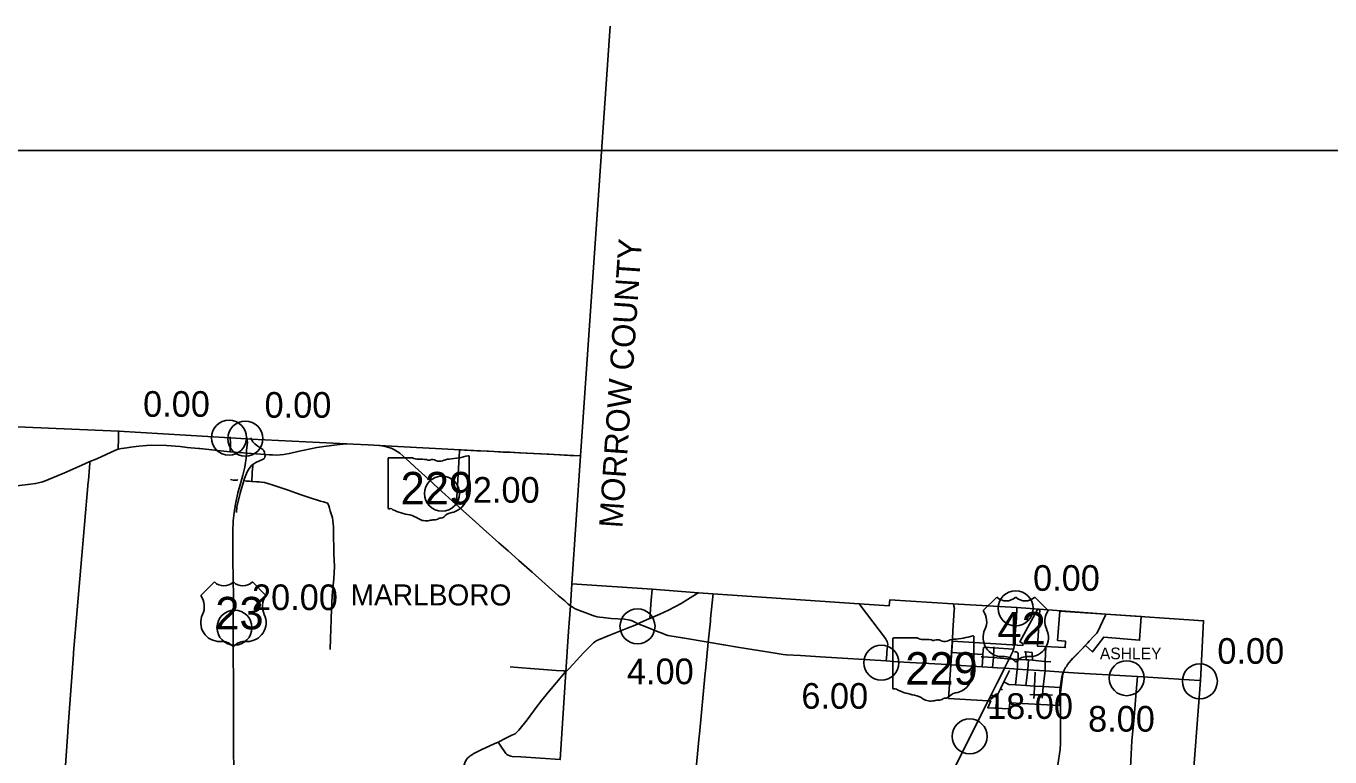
# Model space of a CAD drawing. Extents: x 1597222 to 1925846, y 496284 to 911751.
# Drawn here: x 1799698 to 1855559, y 874016 to 905333 of the extents above; entities that cross this region are included whole.
import ezdxf

# ---------------------------------------------------------------- set-up
doc = ezdxf.new("R2010")
doc.units = 0
for name, color, linetype in [('Default', 7, 'Continuous'), ('GM_X_Adjacent_County', 7, 'Continuous'), ('GM_X_Adjacent_County_Text', 7, 'Continuous'), ('GM_X_City_Street', 7, 'Continuous'), ('GM_X_Corporation', 7, 'Continuous'), ('GM_X_Corporation_Text', 7, 'Continuous'), ('GM_X_County', 7, 'Continuous'), ('GM_X_County_Road', 7, 'Continuous'), ('GM_X_State_Route', 7, 'Continuous'), ('GM_X_State_Shield', 7, 'Continuous'), ('GM_X_Township', 7, 'Continuous'), ('GM_X_Township_Road', 7, 'Continuous'), ('GM_X_Township_Text', 7, 'Continuous'), ('GM_X_US_Route', 7, 'Continuous'), ('GM_X_US_Shield', 7, 'Continuous'), ('SC_Scratch1', 7, 'Continuous')]:
    doc.layers.add(name, color=color, linetype=linetype)

msp = doc.modelspace()

# ---------------------------------------------------------------- linework, layer by layer
at = {"layer": 'Default'}
for centre in [(1808393, 887694), (1808393, 887694), (1809093, 887655), (1809093, 887655), (1817518, 885300), (1842090, 880384), (1842090, 880384), (1808627, 879557), (1825893, 879614), (1836343, 878055), (1846854, 877391), (1849986, 877257), (1849986, 877257), (1840121, 874896)]:
    msp.add_circle(centre, 750, dxfattribs=at)
at = {"layer": 'GM_X_Adjacent_County'}
msp.add_line((1823458, 886911), (1824723, 905333), dxfattribs=at)
at = {"layer": 'GM_X_City_Street'}
for points in [[(1845108, 878825), (1845186, 878908), (1845242, 878975), (1845432, 879171), (1845571, 879323), (1845601, 879368), (1845923, 880061), (1845958, 880137)], [(1840655, 877877), (1840684, 878302), (1840692, 878411), (1840712, 878711)], [(1840712, 878711), (1840771, 878720), (1841162, 878693), (1842005, 878635)], [(1841096, 877846), (1841141, 878272), (1841162, 878693), (1841165, 878729)], [(1843359, 877702), (1843365, 878107), (1843394, 878741)], [(1839341, 878485), (1840692, 878411)], [(1840624, 878310), (1840684, 878302), (1841141, 878272), (1841739, 878225)], [(1841739, 878225), (1841815, 878219), (1842196, 878198), (1842538, 878180), (1842649, 878172), (1842823, 878163), (1843332, 878109)], [(1842195, 878194), (1842196, 878198), (1842207, 878423), (1842204, 878453), (1842189, 878476), (1842156, 878505), (1842118, 878523), (1842051, 878515)], [(1842164, 877756), (1842167, 877780), (1842180, 877986), (1842195, 878194)], [(1842480, 878523), (1842536, 878518), (1842809, 878492)], [(1842531, 877075), (1842621, 877751), (1842649, 878172)], [(1842538, 878180), (1842536, 878518)], [(1842823, 878163), (1842809, 878492)], [(1841290, 876572), (1841275, 876591), (1841439, 876928), (1841591, 877241), (1841826, 877723)], [(1842082, 877102), (1842164, 877756)], [(1842882, 876677), (1842882, 876677), (1842882, 876684), (1842900, 877054), (1842928, 877653)], [(1843238, 876648), (1843241, 876673), (1843277, 877031), (1843359, 877702)], [(1843332, 878109), (1843335, 878108), (1843365, 878107), (1843598, 878093)], [(1841591, 877241), (1841805, 877127), (1842082, 877102), (1842094, 877101), (1842531, 877075), (1842900, 877054), (1843277, 877031), (1843995, 876989)], [(1841039, 876677), (1841303, 876558)], [(1841244, 876119), (1841303, 876558), (1841290, 876572)], [(1841439, 876928), (1841534, 876885)], [(1842709, 876689), (1842882, 876684), (1843220, 876674), (1843220, 876674)], [(1842875, 876522), (1842882, 876677)], [(1843220, 876674), (1843241, 876673), (1843680, 876660)], [(1843230, 876537), (1843238, 876642), (1843238, 876648)]]:
    msp.add_lwpolyline(points, dxfattribs=at)
at = {"layer": 'GM_X_Corporation'}
msp.add_lwpolyline([(1839212, 876522), (1839395, 878979), (1842403, 878797), (1842406, 878874), (1842276, 878944), (1843026, 880333), (1843137, 880326), (1843037, 878758), (1844222, 878701), (1844237, 878976), (1843894, 879006), (1843983, 880269), (1847478, 880034), (1847407, 879013), (1845866, 879149), (1845394, 878513), (1845080, 878796), (1844533, 878238), (1844393, 878064), (1844314, 877970), (1844271, 877898), (1844236, 877846), (1844178, 877730), (1844140, 877653), (1844101, 877578), (1844075, 877468), (1843989, 876865), (1843985, 876781), (1843972, 876227), (1841843, 876336), (1841816, 876073), (1840902, 876121), (1841027, 876414), (1840914, 876421)], close=True, dxfattribs=at)
at = {"layer": 'GM_X_County'}
msp.add_lwpolyline([(1797651, 888237), (1803655, 887971), (1808445, 887685), (1809126, 887642), (1809339, 887629), (1813443, 887429), (1813717, 887422), (1814360, 887388), (1814847, 887358), (1815353, 887328), (1818316, 887169), (1823458, 886911), (1823082, 881429), (1826517, 881205), (1828513, 881052), (1829123, 881005), (1835395, 880574), (1836682, 880495), (1836708, 880754), (1839410, 880574), (1842150, 880416), (1845959, 880135), (1850147, 879854), (1850017, 877290), (1849634, 872258)], dxfattribs=at)
at = {"layer": 'GM_X_County_Road'}
for points in [[(1802428, 886671), (1802725, 886790), (1803530, 887161), (1803639, 887203), (1803789, 887229), (1804010, 887263), (1804184, 887296), (1804528, 887326), (1804861, 887359), (1805077, 887369), (1805715, 887362), (1806296, 887312), (1806604, 887281), (1807079, 887231), (1807143, 887228), (1808298, 887102), (1808443, 887089)], [(1797502, 885545), (1798225, 885516), (1798393, 885518), (1798918, 885581), (1799416, 885645), (1799891, 885700), (1800108, 885729), (1800227, 885756), (1800345, 885789), (1800404, 885808), (1800482, 885836), (1801245, 886152), (1801314, 886180), (1802090, 886513), (1802428, 886671)], [(1801484, 875131), (1801730, 878401), (1801736, 878492), (1802364, 885806), (1802368, 885867), (1802423, 886605), (1802428, 886671)], [(1826404, 879946), (1826423, 879954), (1826844, 880138), (1827215, 880304), (1827767, 880596), (1828264, 880901), (1828526, 881056)], [(1826423, 879954), (1826479, 880739), (1826518, 881195)], [(1825923, 879717), (1825991, 879759), (1826404, 879946)], [(1822822, 877662), (1822979, 877822), (1823573, 878476), (1824013, 878909), (1824059, 878945), (1824151, 879002), (1824217, 879033), (1824631, 879211), (1825422, 879515), (1825871, 879688), (1825923, 879717)], [(1844140, 877653), (1844178, 877730), (1844236, 877846), (1844271, 877898), (1844314, 877970), (1844393, 878064), (1844672, 878363), (1844876, 878580), (1845108, 878825)], [(1818695, 874040), (1818726, 874065), (1818820, 874127), (1818849, 874146), (1819230, 874331), (1819753, 874577), (1819917, 874653), (1820258, 874816), (1820515, 874948), (1820647, 875011), (1820694, 875046), (1820805, 875160), (1821161, 875608), (1821552, 876138), (1821797, 876450), (1822043, 876750), (1822580, 877393), (1822787, 877627), (1822822, 877662)], [(1843903, 873683), (1843995, 874339), (1844011, 874603), (1844010, 875790), (1844011, 876128), (1844012, 876758), (1844119, 877561), (1844140, 877653)], [(1801238, 871613), (1801481, 875086), (1801483, 875120), (1801484, 875131)], [(1820462, 864324), (1820315, 864828), (1820199, 865126), (1819267, 867478), (1819059, 868009), (1819037, 868087), (1819024, 868161), (1818988, 868490), (1818871, 869545), (1818714, 871024), (1818688, 871275), (1818522, 872824), (1818481, 873185), (1818449, 873518), (1818456, 873613), (1818468, 873675), (1818498, 873766), (1818559, 873888), (1818627, 873984), (1818695, 874040)]]:
    msp.add_lwpolyline(points, dxfattribs=at)
at = {"layer": 'GM_X_State_Route'}
for points in [[(1808448, 887738), (1808450, 887411), (1808443, 887089)], [(1808443, 887089), (1808443, 887089), (1809011, 887047), (1809140, 887038)], [(1809140, 887038), (1809351, 887019), (1809932, 886979), (1810132, 886963), (1810262, 886956), (1810420, 886950), (1810584, 886956), (1810738, 886979), (1811036, 887037), (1811335, 887099), (1811536, 887144), (1811949, 887231), (1812149, 887270), (1812265, 887288), (1812452, 887318), (1813005, 887387), (1813408, 887426)], [(1813408, 887426), (1813443, 887429), (1813717, 887422), (1814360, 887388), (1814824, 887360)], [(1814824, 887360), (1814847, 887358), (1815015, 887333), (1815089, 887321), (1815189, 887294), (1815338, 887242), (1815486, 887171), (1815704, 887032), (1815841, 886918), (1816128, 886656), (1816355, 886449), (1816954, 885901), (1817356, 885538), (1818106, 884845), (1818568, 884430), (1818934, 884102), (1819283, 883790), (1819954, 883190), (1820355, 882842), (1820806, 882440), (1821377, 881933), (1822496, 880940), (1822775, 880699), (1822923, 880569), (1823026, 880489), (1823096, 880443), (1823229, 880369), (1823524, 880245), (1823681, 880185), (1823974, 880072), (1824071, 880043), (1824169, 880019), (1824269, 880002), (1824418, 879984), (1824766, 879955), (1825340, 879913), (1825491, 879897), (1825574, 879880), (1825668, 879848), (1825923, 879717), (1826289, 879572), (1826707, 879409), (1826973, 879302), (1827103, 879251), (1827193, 879225), (1827284, 879205), (1827814, 879113), (1828926, 878930), (1829588, 878819), (1830263, 878712), (1831616, 878486), (1831957, 878431), (1832136, 878410), (1832267, 878397), (1832870, 878356), (1833733, 878300), (1836550, 878131), (1837033, 878098), (1838904, 877988), (1839306, 877964)], [(1839306, 877964), (1840655, 877877), (1841096, 877846), (1841303, 877834)], [(1841303, 877834), (1841619, 877817)], [(1841619, 877817), (1842011, 877788), (1842144, 877781)], [(1842144, 877781), (1842167, 877780), (1842611, 877751), (1842621, 877751), (1843359, 877702), (1844140, 877653)], [(1844140, 877653), (1844783, 877609), (1847310, 877457), (1849978, 877293)]]:
    msp.add_lwpolyline(points, dxfattribs=at)
at = {"layer": 'GM_X_State_Shield'}
for p, q in [((1815205, 886800), (1815205, 884687)), ((1815205, 886800), (1815205, 884687)), ((1816258, 886837), (1815239, 886837)), ((1816258, 886837), (1815239, 886837)), ((1818685, 885784), (1818685, 886889)), ((1818685, 885784), (1818685, 886889)), ((1818685, 885784), (1818685, 885784)), ((1818685, 885784), (1818685, 885784)), ((1836826, 879078), (1836826, 876965)), ((1836826, 879078), (1836826, 876965)), ((1837880, 879115), (1836860, 879115)), ((1837880, 879115), (1836860, 879115)), ((1840307, 878062), (1840307, 879167)), ((1840307, 878062), (1840307, 879167)), ((1840306, 878062), (1840307, 878062)), ((1840306, 878062), (1840307, 878062))]:
    msp.add_line(p, q, dxfattribs=at)
for centre, major_axis, start_param, end_param in [((1815244, 886805), (40.3, 0), 1.712693, 3.28349), ((1815244, 886805), (40.3, 0), 1.712693, 3.28349), ((1816501, 887082), (391, 0), 4.042523, 4.731795), ((1816501, 887082), (391, 0), 4.042523, 4.731795), ((1816630, 885650), (1404, 0), 1.404758, 1.657858), ((1816630, 885650), (1404, 0), 1.404758, 1.657858), ((1816949, 886816), (113, 0), 3.836095, 5.185415), ((1816949, 886816), (113, 0), 3.836095, 5.185415), ((1817115, 886572), (235, 0), 0.950623, 2.079405), ((1817115, 886572), (235, 0), 0.950623, 2.079405), ((1817418, 886907), (282, 0), 4.081561, 5.145723), ((1817418, 886907), (282, 0), 4.081561, 5.145723), ((1817916, 886191), (743, 0), 1.699011, 2.107814), ((1817916, 886191), (743, 0), 1.699011, 2.107814), ((1817445, 889718), (3691, 0), 4.814394, 5.042369), ((1817445, 889718), (3691, 0), 4.814394, 5.042369), ((1818646, 886894), (38.7, 0), 6.141152, 7.989035), ((1818646, 886894), (38.7, 0), 6.141152, 7.989035), ((1818824, 885321), (262, 0), 2.387724, 3.262537), ((1818824, 885321), (262, 0), 2.387724, 3.262537), ((1818676, 885703), (60, 0), 1.883978, 3.671073), ((1818676, 885703), (60, 0), 1.883978, 3.671073), ((1818295, 885563), (360, 0), 5.934695, 6.695948), ((1818295, 885563), (360, 0), 5.934695, 6.695948), ((1818644, 885779), (41.5, 0), 5.05454, 6.418171), ((1818644, 885779), (41.5, 0), 5.05454, 6.418171), ((1817652, 885180), (923, 0), 5.101752, 6.440018), ((1817652, 885180), (923, 0), 5.101752, 6.440018), ((1815245, 884683), (40.7, 0), 3.00124, 4.508301), ((1815245, 884683), (40.7, 0), 3.00124, 4.508301), ((1815251, 884899), (310, 0), 4.665946, 4.897461), ((1815251, 884899), (310, 0), 4.665946, 4.897461), ((1815314, 884565), (112, 0), 0.519207, 1.627899), ((1815314, 884565), (112, 0), 0.519207, 1.627899), ((1816728, 886464), (2665, 0), 4.195997, 4.488961), ((1816728, 886464), (2665, 0), 4.195997, 4.488961), ((1815933, 883738), (834, 0), 0.823519, 1.323587), ((1815933, 883738), (834, 0), 0.823519, 1.323587), ((1817401, 884482), (298, 0), 4.937069, 5.64225), ((1817401, 884482), (298, 0), 4.937069, 5.64225), ((1818041, 884094), (506, 0), 1.647645, 2.488434), ((1818041, 884094), (506, 0), 1.647645, 2.488434), ((1816835, 884555), (529, 0), 4.026481, 4.996735), ((1816835, 884555), (529, 0), 4.026481, 4.996735), ((1817141, 883824), (435, 0), 1.495662, 1.94098), ((1817141, 883824), (435, 0), 1.495662, 1.94098), ((1817179, 884397), (282, 0), 4.691044, 5.507374), ((1817179, 884397), (282, 0), 4.691044, 5.507374), ((1817434, 884192), (79.4, 0), 1.147584, 2.315152), ((1817434, 884192), (79.4, 0), 1.147584, 2.315152), ((1836866, 879083), (40.3, 0), 1.712693, 3.28349), ((1836866, 879083), (40.3, 0), 1.712693, 3.28349), ((1838122, 879360), (391, 0), 4.042523, 4.731795), ((1838122, 879360), (391, 0), 4.042523, 4.731795), ((1838252, 877928), (1404, 0), 1.404758, 1.657858), ((1838252, 877928), (1404, 0), 1.404758, 1.657858), ((1838571, 879094), (113, 0), 3.836095, 5.185415), ((1838571, 879094), (113, 0), 3.836095, 5.185415), ((1838736, 878850), (235, 0), 0.950623, 2.079405), ((1838736, 878850), (235, 0), 0.950623, 2.079405), ((1839039, 879185), (282, 0), 4.081561, 5.145723), ((1839039, 879185), (282, 0), 4.081561, 5.145723), ((1839538, 878469), (743, 0), 1.699011, 2.107814), ((1839538, 878469), (743, 0), 1.699011, 2.107814), ((1839067, 881996), (3691, 0), 4.814394, 5.042369), ((1839067, 881996), (3691, 0), 4.814394, 5.042369), ((1840268, 879172), (38.7, 0), 6.141152, 7.989035), ((1840268, 879172), (38.7, 0), 6.141152, 7.989035), ((1840445, 877599), (262, 0), 2.387724, 3.262537), ((1840445, 877599), (262, 0), 2.387724, 3.262537), ((1840298, 877981), (60, 0), 1.883978, 3.671073), ((1840298, 877981), (60, 0), 1.883978, 3.671073), ((1839916, 877841), (360, 0), 5.934695, 6.695948), ((1839916, 877841), (360, 0), 5.934695, 6.695948), ((1840265, 878057), (41.5, 0), 5.05454, 6.418171), ((1840265, 878057), (41.5, 0), 5.05454, 6.418171), ((1839274, 877458), (923, 0), 5.101752, 6.440018), ((1839274, 877458), (923, 0), 5.101752, 6.440018), ((1836866, 876961), (40.7, 0), 3.00124, 4.508301), ((1836866, 876961), (40.7, 0), 3.00124, 4.508301), ((1836873, 877177), (310, 0), 4.665946, 4.897461), ((1836873, 877177), (310, 0), 4.665946, 4.897461), ((1836936, 876843), (112, 0), 0.519207, 1.627899), ((1836936, 876843), (112, 0), 0.519207, 1.627899), ((1838349, 878742), (2665, 0), 4.195997, 4.488961), ((1838349, 878742), (2665, 0), 4.195997, 4.488961), ((1837555, 876016), (834, 0), 0.823519, 1.323587), ((1837555, 876016), (834, 0), 0.823519, 1.323587), ((1838457, 876833), (529, 0), 4.026481, 4.996735), ((1838457, 876833), (529, 0), 4.026481, 4.996735), ((1838801, 876675), (282, 0), 4.691044, 5.507374), ((1838801, 876675), (282, 0), 4.691044, 5.507374), ((1839056, 876470), (79.4, 0), 1.147584, 2.315152), ((1839056, 876470), (79.4, 0), 1.147584, 2.315152), ((1839022, 876760), (298, 0), 4.937069, 5.64225), ((1839022, 876760), (298, 0), 4.937069, 5.64225), ((1839663, 876372), (506, 0), 1.647645, 2.488434), ((1839663, 876372), (506, 0), 1.647645, 2.488434), ((1838762, 876102), (435, 0), 1.495662, 1.94098), ((1838762, 876102), (435, 0), 1.495662, 1.94098)]:
    msp.add_ellipse(centre, major_axis=major_axis, ratio=0.8, start_param=start_param, end_param=end_param, dxfattribs=at)
at = {"layer": 'GM_X_Township'}
for points in [[(1822583, 873901), (1822822, 877662), (1822932, 879384), (1823026, 880489), (1823082, 881429)], [(1850147, 879854), (1850017, 877290), (1849634, 872258)]]:
    msp.add_lwpolyline(points, dxfattribs=at)
at = {"layer": 'GM_X_Township_Road'}
for points in [[(1803639, 887203), (1803654, 887676), (1803660, 888000)], [(1809932, 886979), (1809918, 887050), (1809907, 887094), (1809888, 887135), (1809878, 887151), (1809840, 887193), (1809801, 887219), (1809584, 887360), (1809495, 887435), (1809449, 887480), (1809413, 887519), (1809392, 887551), (1809310, 887690)], [(1818106, 884845), (1818121, 884859), (1818133, 884883), (1818136, 884905), (1818252, 886879), (1818267, 887127), (1818268, 887136), (1818271, 887143), (1818274, 887150), (1818280, 887162)], [(1818280, 887162), (1818283, 887165), (1818289, 887169), (1818299, 887170), (1818316, 887171), (1818334, 887171), (1818481, 887161), (1819006, 887135), (1819514, 887112), (1819744, 887102), (1820121, 887082), (1820432, 887068), (1820842, 887046), (1821432, 887018), (1822088, 886984), (1822989, 886935), (1823461, 886911)], [(1808984, 885705), (1809011, 885796), (1809034, 885855), (1809061, 885951), (1809170, 886226), (1809206, 886304), (1809251, 886376), (1809294, 886437), (1809358, 886504), (1809406, 886542), (1809454, 886576), (1809542, 886627), (1809831, 886763), (1809881, 886792), (1809913, 886825), (1809931, 886870), (1809935, 886910), (1809932, 886979)], [(1809386, 886211), (1809409, 886473), (1809406, 886542)], [(1809364, 885824), (1809383, 886171), (1809386, 886211)], [(1808454, 885901), (1808566, 885881), (1808684, 885871), (1808743, 885873), (1808777, 885905)], [(1808714, 884485), (1808722, 884731), (1808722, 884738), (1808750, 884850), (1808872, 885317), (1808915, 885473), (1808938, 885554), (1808984, 885705)], [(1809034, 885855), (1809142, 885837), (1809263, 885827), (1809364, 885824), (1809568, 885807), (1809684, 885798), (1809773, 885791), (1809914, 885774), (1810011, 885752), (1810278, 885666), (1810454, 885608), (1810925, 885443), (1811247, 885331), (1811523, 885237)], [(1811523, 885237), (1811827, 885133), (1812317, 884973), (1812441, 884940), (1812528, 884920), (1812580, 884904), (1812610, 884886), (1812639, 884853), (1812664, 884782), (1812698, 884680), (1812730, 884568), (1812770, 884428), (1812820, 884266), (1812840, 884152), (1812859, 883988), (1812870, 883884), (1812870, 883618), (1812883, 882825), (1812883, 882752), (1812905, 882162), (1812885, 881655), (1812818, 880932), (1812765, 879975), (1812762, 879888), (1812743, 879096), (1812732, 878621)], [(1828926, 878930), (1829014, 879840), (1829023, 879943), (1829130, 881016)], [(1836550, 878131), (1836572, 878407), (1836577, 878507), (1836605, 878769), (1836613, 878847), (1836605, 878899), (1836595, 878967), (1836565, 879011), (1836515, 879086), (1835436, 880521), (1835397, 880584)], [(1839306, 877964), (1839341, 878485), (1839399, 879352), (1839403, 879417), (1839467, 880312), (1839471, 880374), (1839440, 880475), (1839429, 880574)], [(1828404, 873550), (1828535, 874900), (1828545, 874985), (1828797, 877614), (1828805, 877701), (1828926, 878930)], [(1820435, 877874), (1820766, 877848), (1821496, 877793), (1822410, 877722), (1822732, 877701), (1822772, 877694), (1822797, 877688), (1822822, 877662)], [(1846952, 868642), (1846950, 869189), (1846940, 869904), (1846940, 870264), (1846936, 871157), (1846927, 871876), (1846924, 872189), (1846924, 872391), (1846924, 872409), (1846974, 873096), (1847017, 873560), (1847077, 874700), (1847167, 875719), (1847252, 876799), (1847310, 877457)], [(1819917, 874653), (1820070, 874430), (1820190, 874250), (1820246, 874169), (1820290, 874124), (1820359, 874086), (1820425, 874058), (1820460, 874051)], [(1820460, 874051), (1820518, 874039), (1820891, 874015), (1822583, 873901), (1822593, 873900)]]:
    msp.add_lwpolyline(points, dxfattribs=at)
at = {"layer": 'GM_X_US_Route'}
for points in [[(1808684, 884925), (1808774, 885335), (1808893, 885780), (1808982, 886093), (1809032, 886266), (1809069, 886438), (1809101, 886628), (1809127, 886805), (1809140, 887038), (1809140, 887166), (1809178, 887493), (1809158, 887698)], [(1808573, 884088), (1808574, 884127), (1808608, 884480), (1808669, 884858), (1808684, 884925)], [(1808559, 883718), (1808573, 884088)], [(1808595, 873359), (1808593, 873477), (1808580, 874305), (1808584, 874680), (1808589, 875164), (1808584, 876236), (1808583, 877272), (1808564, 878356), (1808567, 879838), (1808589, 880869), (1808563, 882458), (1808556, 883637), (1808559, 883718)], [(1842050, 878929), (1842054, 878989), (1842074, 879275), (1842125, 879970), (1842151, 880391)], [(1842000, 878620), (1842005, 878635), (1842013, 878659), (1842035, 878764), (1842042, 878816), (1842050, 878929)], [(1841619, 877817), (1841815, 878219), (1841969, 878528), (1842000, 878620)], [(1841285, 877158), (1841355, 877293), (1841619, 877817)], [(1840905, 876404), (1840914, 876421), (1841039, 876677), (1841285, 877158)], [(1832814, 860270), (1833045, 860728), (1833707, 862039), (1833995, 862623), (1834269, 863162), (1835215, 865051), (1835681, 865996), (1836078, 866774), (1836442, 867502), (1837331, 869279), (1837642, 869882), (1838022, 870648), (1838475, 871555), (1838873, 872351), (1839135, 872864), (1840316, 875226), (1840905, 876404)]]:
    msp.add_lwpolyline(points, dxfattribs=at)
at = {"layer": 'GM_X_US_Shield'}
for p, q in [((1807768, 881512), (1807188, 880932)), ((1807768, 881512), (1807188, 880932)), ((1809972, 880932), (1809392, 881512)), ((1809972, 880932), (1809392, 881512)), ((1841287, 880866), (1840707, 880285)), ((1841287, 880866), (1840707, 880285)), ((1843491, 880285), (1842911, 880866)), ((1843491, 880285), (1842911, 880866)), ((1808000, 878960), (1808116, 878960)), ((1808000, 878960), (1808116, 878960)), ((1809044, 878960), (1809160, 878960)), ((1809044, 878960), (1809160, 878960)), ((1841519, 878313), (1841635, 878313)), ((1841519, 878313), (1841635, 878313)), ((1842563, 878313), (1842679, 878313)), ((1842563, 878313), (1842679, 878313))]:
    msp.add_line(p, q, dxfattribs=at)
for centre, radius, start, end in [((1808174, 881927), 580, 225.573, 314.427), ((1808174, 881927), 580, 225.573, 314.427), ((1808986, 881927), 580, 225.573, 314.427), ((1808986, 881927), 580, 225.573, 314.427), ((1806523, 880466), 812, 334.5471, 35.0009), ((1806523, 880466), 812, 334.5471, 35.0009), ((1810637, 880466), 812, 144.9991, 205.4529), ((1810637, 880466), 812, 144.9991, 205.4529), ((1841693, 881280), 580, 225.573, 314.427), ((1841693, 881280), 580, 225.573, 314.427), ((1842505, 881280), 580, 225.573, 314.427), ((1842505, 881280), 580, 225.573, 314.427), ((1807991, 879772), 812, 154.8319, 270.6383), ((1807991, 879772), 812, 154.8319, 270.6383), ((1809169, 879772), 812, 269.3617, 25.1681), ((1809169, 879772), 812, 269.3617, 25.1681), ((1840042, 879820), 812, 334.5471, 35.0009), ((1840042, 879820), 812, 334.5471, 35.0009), ((1844157, 879820), 812, 144.9991, 205.4529), ((1844157, 879820), 812, 144.9991, 205.4529), ((1841510, 879125), 812, 154.8319, 270.6383), ((1841510, 879125), 812, 154.8319, 270.6383), ((1842688, 879125), 812, 269.3617, 25.1681), ((1842688, 879125), 812, 269.3617, 25.1681), ((1808116, 878380), 580, 36.8699, 90), ((1808116, 878380), 580, 36.8699, 90), ((1809044, 878380), 580, 90, 143.1301), ((1809044, 878380), 580, 90, 143.1301), ((1841635, 877733), 580, 36.8699, 90), ((1841635, 877733), 580, 36.8699, 90), ((1842563, 877733), 580, 90, 143.1301), ((1842563, 877733), 580, 90, 143.1301)]:
    msp.add_arc(centre, radius, start, end, dxfattribs=at)
at = {"layer": 'SC_Scratch1'}
msp.add_lwpolyline([(1729596, 899996), (1925846, 899996), (1925846, 765496), (1729596, 765496)], close=True, dxfattribs=at)

# ---------------------------------------------------------------- texts
at = {"layer": 'Default'}
for s, p in [('0.00', (1804711, 888590)), ('0.00', (1809915, 888550)), ('2.00', (1818838, 884909)), ('0.00', (1842840, 881134)), ('20.00', (1809377, 880307)), ('0.00', (1850736, 878007)), ('4.00', (1825439, 877133)), ('6.00', (1832913, 876081)), ('18.00', (1840871, 875646)), ('8.00', (1845197, 875100))]:
    msp.add_text(s, height=1100, dxfattribs=at).set_placement(p)
at = {"layer": 'GM_X_Adjacent_County_Text'}
msp.add_text('MORROW COUNTY', height=1000, rotation=86.0902, dxfattribs=at).set_placement((1825240, 883804))
at = {"layer": 'GM_X_Corporation_Text'}
msp.add_text('ASHLEY', height=500, rotation=0, dxfattribs=at).set_placement((1845704, 878201))
at = {"layer": 'GM_X_State_Shield'}
for p in [(1815744, 884836), (1815744, 884836), (1837366, 877114), (1837366, 877114)]:
    msp.add_text('229', height=1392.2, dxfattribs=at).set_placement(p)
at = {"layer": 'GM_X_Township_Text'}
msp.add_text('MARLBORO', height=900, rotation=0, dxfattribs=at).set_placement((1813603, 880507))
at = {"layer": 'GM_X_US_Shield'}
for s, p in [('23', (1807805, 879482)), ('23', (1807805, 879482)), ('42', (1841315, 878835)), ('42', (1841315, 878835))]:
    msp.add_text(s, height=1392.2, dxfattribs=at).set_placement(p)

doc.saveas('drawing.dxf')
